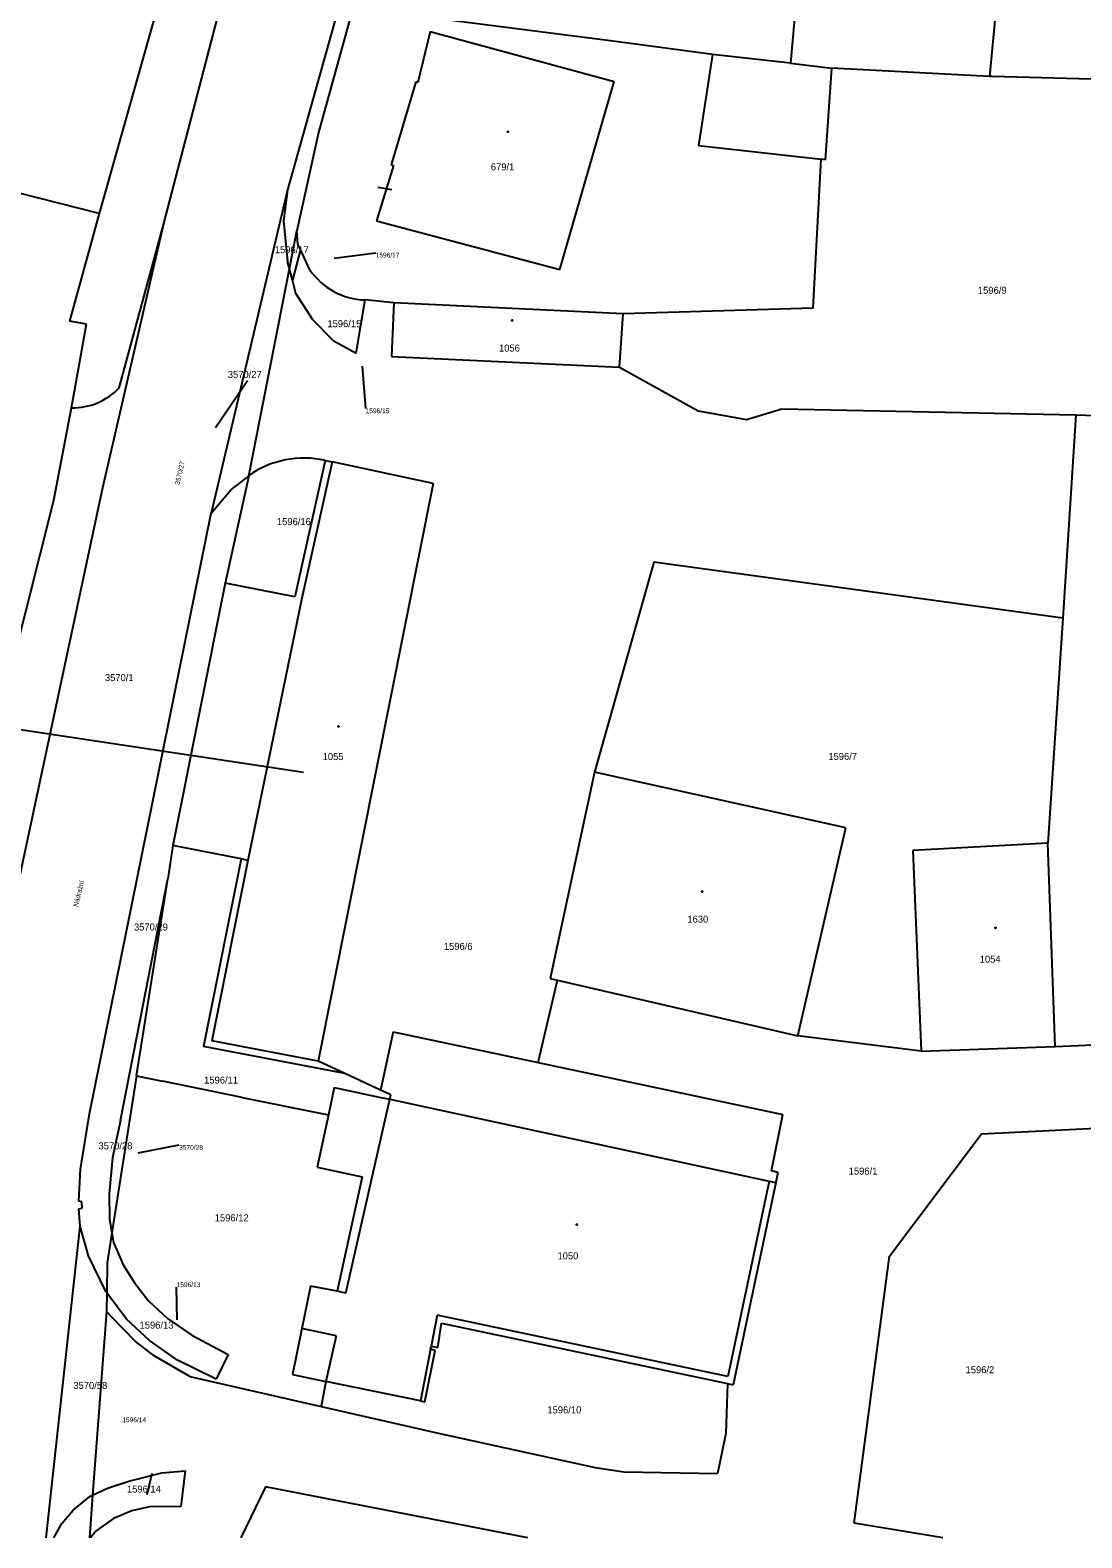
# Model space of a CAD drawing. Extents: x -866624 to -866276, y -1050208 to -1049940.
# Drawn here: x -866468.3 to -866393.3, y -1050208.1 to -1050100.7 of the extents above; entities that cross this region are included whole.
import ezdxf

# ---------------------------------------------------------------- set-up
doc = ezdxf.new("R2010")
doc.units = 0
for name, color, linetype in [('_FORMATY', 7, 'Continuous'), ('Default', 7, 'Continuous'), ('Hranice', 7, 'Continuous'), ('Hranice další', 7, 'Continuous'), ('Hranice-budov', 7, 'Continuous'), ('nazvy-ulic-tok', 7, 'Continuous'), ('Parcela-pozemkova', 7, 'Continuous'), ('Parcela-stavebni', 7, 'Continuous'), ('Parcelni-cisla-pomocna', 7, 'Continuous'), ('znacky-budov', 7, 'Continuous')]:
    doc.layers.add(name, color=color, linetype=linetype)

# ---------------------------------------------------------------- blocks, each defined once
blk = doc.blocks.new('s_zdena')
at = {"layer": 'Default'}
blk.add_circle((0, 0), 0.175, dxfattribs=at)
for start, end in [(0, 180), (180, 0)]:
    blk.add_arc((0, 0), 0.0875, start, end, dxfattribs=at)

msp = doc.modelspace()

# ---------------------------------------------------------------- linework, layer by layer
at = {"layer": '_FORMATY'}
for p, q in [((-866442.54, -1050112.04), (-866443.53, -1050111.89)), ((-866507.55, -1050144.69), (-866448.82, -1050153.56))]:
    msp.add_line(p, q, dxfattribs=at)
at = {"layer": 'Hranice'}
for p, q in [((-866439.93, -1050076.25), (-866449.97, -1050112.04)), ((-866457.96, -1050094.49), (-866463.4, -1050113.74)), ((-866458.78, -1050114.45), (-866453.82, -1050095.39)), ((-866413.54, -1050096.51), (-866414.11, -1050103.03)), ((-866445.48, -1050099.71), (-866447.75, -1050107.96)), ((-866426.4, -1050101.5), (-866441.63, -1050099.54)), ((-866419.67, -1050102.39), (-866426.4, -1050101.5)), ((-866414.11, -1050103.03), (-866419.67, -1050102.39)), ((-866414.11, -1050103.03), (-866411.18, -1050103.37)), ((-866411.18, -1050103.37), (-866411.64, -1050109.92)), ((-866399.92, -1050103.96), (-866411.18, -1050103.37)), ((-866399.74, -1050103.97), (-866399.92, -1050103.96)), ((-866361.55, -1050105.03), (-866399.74, -1050103.97)), ((-866447.75, -1050107.96), (-866449.3, -1050114.98)), ((-866412.49, -1050120.49), (-866411.93, -1050109.87)), ((-866411.64, -1050109.92), (-866411.93, -1050109.87)), ((-866463.4, -1050113.74), (-866470.72, -1050111.89)), ((-866449.97, -1050112.04), (-866455.4, -1050135.11)), ((-866449.97, -1050112.04), (-866450.26, -1050114.25)), ((-866463.4, -1050113.74), (-866465.5, -1050121.42)), ((-866450.26, -1050114.25), (-866449.97, -1050117.16)), ((-866463.14, -1050133.28), (-866458.78, -1050114.45)), ((-866461.96, -1050126.16), (-866458.78, -1050114.45)), ((-866449.83, -1050117.68), (-866449.3, -1050114.98)), ((-866449.24, -1050115.91), (-866449.3, -1050114.98)), ((-866449.05, -1050116.31), (-866449.62, -1050118.48)), ((-866449.05, -1050116.31), (-866449.24, -1050115.91)), ((-866448.37, -1050117.75), (-866449.05, -1050116.31)), ((-866449.83, -1050117.68), (-866449.97, -1050117.16)), ((-866452.73, -1050132.43), (-866449.83, -1050117.68)), ((-866449.62, -1050118.48), (-866449.83, -1050117.68)), ((-866449.36, -1050119.44), (-866449.62, -1050118.48)), ((-866448.15, -1050121.32), (-866449.36, -1050119.44)), ((-866445.07, -1050123.7), (-866444.43, -1050119.9)), ((-866442.38, -1050120.11), (-866444.43, -1050119.9)), ((-866442.38, -1050120.11), (-866442.56, -1050123.94)), ((-866426.04, -1050120.9), (-866442.38, -1050120.11)), ((-866412.49, -1050120.49), (-866426.04, -1050120.9)), ((-866464.29, -1050121.63), (-866465.5, -1050121.42)), ((-866465.37, -1050127.59), (-866464.29, -1050121.63)), ((-866446.7, -1050122.79), (-866448.15, -1050121.32)), ((-866426.3, -1050124.7), (-866426.04, -1050120.9)), ((-866446.7, -1050122.79), (-866445.07, -1050123.7)), ((-866442.56, -1050123.94), (-866426.3, -1050124.7)), ((-866426.3, -1050124.7), (-866420.7, -1050127.81)), ((-866466.62, -1050134.17), (-866465.37, -1050127.59)), ((-866420.7, -1050127.81), (-866417.25, -1050128.43)), ((-866417.25, -1050128.43), (-866414.73, -1050127.67)), ((-866414.73, -1050127.67), (-866393.77, -1050128.08)), ((-866393.77, -1050128.08), (-866394.7, -1050142.59)), ((-866393.77, -1050128.08), (-866384.76, -1050128.41)), ((-866447.28, -1050131.34), (-866449.44, -1050141.06)), ((-866447.28, -1050131.34), (-866446.79, -1050131.44)), ((-866439.57, -1050132.99), (-866446.79, -1050131.44)), ((-866452.73, -1050132.43), (-866454.42, -1050140.08)), ((-866452.73, -1050132.43), (-866453.96, -1050133.39)), ((-866470.92, -1050169.71), (-866463.14, -1050133.28)), ((-866455.4, -1050135.11), (-866453.96, -1050133.39)), ((-866439.57, -1050132.99), (-866447.77, -1050174.17)), ((-866469.64, -1050146.17), (-866466.62, -1050134.17)), ((-866464.08, -1050177.93), (-866455.4, -1050135.11)), ((-866423.85, -1050138.6), (-866428.09, -1050153.56)), ((-866394.7, -1050142.59), (-866423.85, -1050138.6)), ((-866454.42, -1050140.08), (-866458.13, -1050158.79)), ((-866449.44, -1050141.06), (-866454.42, -1050140.08)), ((-866394.7, -1050142.59), (-866395.76, -1050158.62)), ((-866428.09, -1050153.56), (-866431.25, -1050168.28)), ((-866410.17, -1050157.53), (-866428.09, -1050153.56)), ((-866413.58, -1050172.35), (-866410.17, -1050157.53)), ((-866458.13, -1050158.79), (-866458.5, -1050161.17)), ((-866453.28, -1050159.75), (-866458.13, -1050158.79)), ((-866395.76, -1050158.62), (-866405.39, -1050159.15)), ((-866405.39, -1050159.15), (-866404.79, -1050173.45)), ((-866395.24, -1050173.11), (-866395.76, -1050158.62)), ((-866453.28, -1050159.75), (-866455.96, -1050173.12)), ((-866461.88, -1050178.4), (-866458.5, -1050161.17)), ((-866460.72, -1050175.21), (-866458.5, -1050161.17)), ((-866432.09, -1050174.26), (-866430.72, -1050168.4)), ((-866431.25, -1050168.28), (-866430.72, -1050168.4)), ((-866430.72, -1050168.4), (-866413.58, -1050172.35)), ((-866442.44, -1050172.07), (-866443.33, -1050176.24)), ((-866442.44, -1050172.07), (-866432.09, -1050174.26)), ((-866404.79, -1050173.45), (-866413.58, -1050172.35)), ((-866395.24, -1050173.11), (-866377.47, -1050172.35)), ((-866445.88, -1050175.05), (-866455.96, -1050173.12)), ((-866404.79, -1050173.45), (-866395.24, -1050173.11)), ((-866445.88, -1050175.05), (-866447.77, -1050174.17)), ((-866432.09, -1050174.26), (-866414.65, -1050177.96)), ((-866460.72, -1050175.21), (-866462.48, -1050186.4)), ((-866460.72, -1050175.21), (-866458.88, -1050175.59)), ((-866453.2, -1050176.75), (-866458.88, -1050175.59)), ((-866443.33, -1050176.24), (-866445.88, -1050175.05)), ((-866446.63, -1050176.04), (-866447.05, -1050177.99)), ((-866446.63, -1050176.04), (-866443.43, -1050176.72)), ((-866442.61, -1050176.57), (-866443.33, -1050176.24)), ((-866442.68, -1050176.88), (-866442.61, -1050176.57)), ((-866453.2, -1050176.75), (-866447.05, -1050177.99)), ((-866443.43, -1050176.72), (-866442.68, -1050176.88)), ((-866400.49, -1050179.35), (-866363.72, -1050177.49)), ((-866464.73, -1050181.87), (-866464.08, -1050177.93)), ((-866461.88, -1050178.4), (-866462.45, -1050181.02)), ((-866447.05, -1050177.99), (-866447.84, -1050181.72)), ((-866415.46, -1050181.99), (-866414.65, -1050177.96)), ((-866407.05, -1050188.06), (-866400.49, -1050179.35)), ((-866464.85, -1050184.15), (-866464.73, -1050181.87)), ((-866462.45, -1050181.02), (-866462.67, -1050183.63)), ((-866447.84, -1050181.72), (-866444.64, -1050182.4)), ((-866415, -1050182.1), (-866415.46, -1050181.99)), ((-866444.64, -1050182.4), (-866446.42, -1050190.57)), ((-866415.15, -1050182.82), (-866418.19, -1050197.23)), ((-866415, -1050182.1), (-866415.15, -1050182.82)), ((-866464.63, -1050184.19), (-866464.85, -1050184.15)), ((-866464.61, -1050184.64), (-866464.63, -1050184.19)), ((-866462.67, -1050183.63), (-866462.66, -1050185.42)), ((-866464.85, -1050184.69), (-866464.61, -1050184.64)), ((-866464.74, -1050185.93), (-866464.85, -1050184.69)), ((-866467.17, -1050208.15), (-866464.74, -1050185.93)), ((-866464.15, -1050188.03), (-866464.74, -1050185.93)), ((-866462.66, -1050185.42), (-866462.48, -1050186.4)), ((-866462.48, -1050186.4), (-866462.82, -1050188.54)), ((-866462.48, -1050186.4), (-866462.36, -1050187.09)), ((-866462.36, -1050187.09), (-866461.69, -1050188.68)), ((-866462.92, -1050190.59), (-866464.15, -1050188.03)), ((-866409.56, -1050207.1), (-866407.05, -1050188.06)), ((-866462.82, -1050188.54), (-866462.84, -1050190.69)), ((-866461.69, -1050188.68), (-866460.85, -1050189.99)), ((-866462.84, -1050190.69), (-866462.92, -1050190.59)), ((-866460.85, -1050189.99), (-866459.87, -1050191.25)), ((-866448.32, -1050190.21), (-866448.94, -1050193.22)), ((-866446.42, -1050190.57), (-866448.32, -1050190.21)), ((-866462.84, -1050190.69), (-866462.86, -1050192.02)), ((-866461.45, -1050192.56), (-866462.84, -1050190.69)), ((-866459.87, -1050191.25), (-866458.52, -1050192.51)), ((-866462.86, -1050192.02), (-866463.86, -1050205.1)), ((-866462.86, -1050192.02), (-866462.51, -1050192.39)), ((-866462.51, -1050192.39), (-866460.83, -1050194.12)), ((-866459.81, -1050194.08), (-866461.45, -1050192.56)), ((-866458.52, -1050192.51), (-866456.79, -1050193.7)), ((-866456.79, -1050193.7), (-866454.19, -1050195.07)), ((-866448.94, -1050193.22), (-866449.61, -1050196.5)), ((-866439.26, -1050194.58), (-866438.98, -1050192.84)), ((-866438.98, -1050192.84), (-866418.6, -1050197.15)), ((-866459.46, -1050195.17), (-866460.83, -1050194.12)), ((-866457.8, -1050195.49), (-866459.81, -1050194.08)), ((-866440.18, -1050198.44), (-866439.43, -1050194.78)), ((-866439.77, -1050194.7), (-866439.73, -1050194.49)), ((-866439.43, -1050194.78), (-866439.77, -1050194.7)), ((-866439.73, -1050194.49), (-866439.26, -1050194.58)), ((-866456.93, -1050196.65), (-866459.46, -1050195.17)), ((-866455.05, -1050196.84), (-866457.8, -1050195.49)), ((-866454.19, -1050195.07), (-866455.05, -1050196.84)), ((-866456.93, -1050196.65), (-866447.56, -1050198.78)), ((-866449.61, -1050196.5), (-866447.23, -1050196.99)), ((-866447.23, -1050196.99), (-866447.56, -1050198.78)), ((-866440.48, -1050198.38), (-866447.23, -1050196.99)), ((-866418.6, -1050197.15), (-866418.73, -1050200.71)), ((-866418.6, -1050197.15), (-866418.19, -1050197.23)), ((-866447.56, -1050198.78), (-866439.1, -1050200.7)), ((-866440.48, -1050198.38), (-866440.18, -1050198.44)), ((-866439.1, -1050200.7), (-866428.03, -1050203.13)), ((-866418.73, -1050200.71), (-866419.32, -1050203.56)), ((-866461.28, -1050204.1), (-866458.92, -1050203.51)), ((-866458.92, -1050203.51), (-866457.26, -1050203.36)), ((-866457.26, -1050203.36), (-866457.58, -1050205.91)), ((-866428.03, -1050203.13), (-866426, -1050203.44)), ((-866426, -1050203.44), (-866419.32, -1050203.56)), ((-866463.86, -1050205.1), (-866462.8, -1050204.6)), ((-866462.8, -1050204.6), (-866461.28, -1050204.1)), ((-866451.53, -1050204.52), (-866453.29, -1050208.15)), ((-866432.83, -1050208.15), (-866451.53, -1050204.52)), ((-866465.25, -1050206.18), (-866464.05, -1050205.19)), ((-866463.86, -1050205.1), (-866464.09, -1050208.15)), ((-866464.05, -1050205.19), (-866463.86, -1050205.1)), ((-866466.06, -1050207.13), (-866465.25, -1050206.18)), ((-866462.37, -1050206.77), (-866463.61, -1050207.64)), ((-866461.06, -1050206.23), (-866462.37, -1050206.77)), ((-866459.8, -1050205.93), (-866461.06, -1050206.23)), ((-866457.58, -1050205.91), (-866459.8, -1050205.93)), ((-866466.63, -1050208.15), (-866466.06, -1050207.13)), ((-866463.61, -1050207.64), (-866464.02, -1050208.15)), ((-866403.26, -1050208.15), (-866409.56, -1050207.1))]:
    msp.add_line(p, q, dxfattribs=at)
for centre, radius, start, end in [((-866444.3, -1050114.97), 4.93, 214.2918, 268.4669), ((-866465.29, -1050122.99), 4.6, 269.0646, 316.4374), ((-866448.79, -1050137.98), 6.81, 77.225, 125.3949)]:
    msp.add_arc(centre, radius, start, end, dxfattribs=at)
at = {"layer": 'Hranice další'}
for p, q in [((-866399.34, -1050097.9), (-866399.92, -1050103.96)), ((-866439.79, -1050100.75), (-866440.67, -1050104.39)), ((-866439.79, -1050100.75), (-866426.67, -1050104.32)), ((-866419.67, -1050102.39), (-866420.66, -1050108.88)), ((-866440.82, -1050104.35), (-866442.57, -1050110.27)), ((-866440.67, -1050104.39), (-866440.82, -1050104.35)), ((-866430.55, -1050117.72), (-866426.67, -1050104.32)), ((-866420.66, -1050108.88), (-866411.93, -1050109.87)), ((-866442.42, -1050110.31), (-866443.61, -1050114.25)), ((-866442.57, -1050110.27), (-866442.42, -1050110.31)), ((-866443.61, -1050114.25), (-866430.55, -1050117.72)), ((-866446.79, -1050131.44), (-866448.95, -1050141.16)), ((-866448.95, -1050141.16), (-866452.79, -1050159.85)), ((-866452.79, -1050159.85), (-866455.37, -1050172.72)), ((-866452.79, -1050159.85), (-866453.28, -1050159.75)), ((-866447.77, -1050174.17), (-866455.37, -1050172.72)), ((-866445.81, -1050190.7), (-866442.68, -1050176.88)), ((-866442.68, -1050176.88), (-866415.64, -1050182.72)), ((-866415.64, -1050182.72), (-866418.58, -1050196.64)), ((-866415.64, -1050182.72), (-866415.15, -1050182.82)), ((-866445.81, -1050190.7), (-866446.42, -1050190.57)), ((-866439.3, -1050192.26), (-866439.73, -1050194.49)), ((-866418.58, -1050196.64), (-866439.3, -1050192.26)), ((-866446.5, -1050193.75), (-866448.94, -1050193.22)), ((-866446.5, -1050193.75), (-866447.23, -1050196.99)), ((-866439.77, -1050194.7), (-866440.48, -1050198.38))]:
    msp.add_line(p, q, dxfattribs=at)
at = {"layer": 'Hranice-budov'}
for p, q in [((-866439.79, -1050100.75), (-866440.67, -1050104.39)), ((-866439.79, -1050100.75), (-866426.67, -1050104.32)), ((-866440.82, -1050104.35), (-866442.57, -1050110.27)), ((-866440.67, -1050104.39), (-866440.82, -1050104.35)), ((-866430.55, -1050117.72), (-866426.67, -1050104.32)), ((-866442.42, -1050110.31), (-866443.61, -1050114.25)), ((-866442.57, -1050110.27), (-866442.42, -1050110.31)), ((-866443.61, -1050114.25), (-866430.55, -1050117.72)), ((-866442.38, -1050120.11), (-866442.56, -1050123.94)), ((-866426.04, -1050120.9), (-866442.38, -1050120.11)), ((-866426.3, -1050124.7), (-866426.04, -1050120.9)), ((-866442.56, -1050123.94), (-866426.3, -1050124.7)), ((-866446.79, -1050131.44), (-866448.95, -1050141.16)), ((-866439.57, -1050132.99), (-866446.79, -1050131.44)), ((-866439.57, -1050132.99), (-866447.77, -1050174.17)), ((-866448.95, -1050141.16), (-866452.79, -1050159.85)), ((-866428.09, -1050153.56), (-866431.25, -1050168.28)), ((-866410.17, -1050157.53), (-866428.09, -1050153.56)), ((-866413.58, -1050172.35), (-866410.17, -1050157.53)), ((-866395.76, -1050158.62), (-866405.39, -1050159.15)), ((-866405.39, -1050159.15), (-866404.79, -1050173.45)), ((-866395.24, -1050173.11), (-866395.76, -1050158.62)), ((-866452.79, -1050159.85), (-866455.37, -1050172.72)), ((-866431.25, -1050168.28), (-866430.72, -1050168.4)), ((-866430.72, -1050168.4), (-866413.58, -1050172.35)), ((-866447.77, -1050174.17), (-866455.37, -1050172.72)), ((-866404.79, -1050173.45), (-866395.24, -1050173.11)), ((-866445.81, -1050190.7), (-866442.68, -1050176.88)), ((-866442.68, -1050176.88), (-866415.64, -1050182.72)), ((-866415.64, -1050182.72), (-866418.58, -1050196.64)), ((-866448.32, -1050190.21), (-866448.94, -1050193.22)), ((-866446.42, -1050190.57), (-866448.32, -1050190.21)), ((-866445.81, -1050190.7), (-866446.42, -1050190.57)), ((-866439.3, -1050192.26), (-866439.73, -1050194.49)), ((-866418.58, -1050196.64), (-866439.3, -1050192.26)), ((-866446.5, -1050193.75), (-866448.94, -1050193.22)), ((-866446.5, -1050193.75), (-866447.23, -1050196.99)), ((-866439.77, -1050194.7), (-866440.48, -1050198.38)), ((-866439.77, -1050194.7), (-866439.73, -1050194.49)), ((-866440.48, -1050198.38), (-866447.23, -1050196.99))]:
    msp.add_line(p, q, dxfattribs=at)
at = {"layer": 'Parcelni-cisla-pomocna'}
for p, q in [((-866446.65, -1050116.91), (-866443.68, -1050116.53)), ((-866444.64, -1050124.61), (-866444.4, -1050127.63)), ((-866455.09, -1050128.98), (-866452.81, -1050125.63)), ((-866460.6, -1050180.71), (-866457.69, -1050180.14)), ((-866457.83, -1050192.6), (-866457.87, -1050190.27)), ((-866459.64, -1050203.57), (-866459.99, -1050205.09))]:
    msp.add_line(p, q, dxfattribs=at)

# ---------------------------------------------------------------- block references
at = {"layer": 'znacky-budov', "xscale": 0.2, "yscale": 0.20000000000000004}
for p in [(-866434.26, -1050107.91), (-866433.94, -1050121.36), (-866446.34, -1050150.3), (-866420.41, -1050162.07), (-866399.5, -1050164.67), (-866429.33, -1050185.81)]:
    msp.add_blockref('s_zdena', p, dxfattribs=at)

# ---------------------------------------------------------------- texts
at = {"layer": 'nazvy-ulic-tok'}
msp.add_text('Nádražní', height=0.34, rotation=76.6916, dxfattribs=at).set_placement((-866464.91, -1050163.19))
at = {"layer": 'Parcela-pozemkova'}
for s, p in [('1596/17', (-866450.87, -1050116.57)), ('1596/9', (-866400.75, -1050119.46)), ('1596/15', (-866447.12, -1050121.84)), ('3570/27', (-866454.22, -1050125.46)), ('1596/16', (-866450.72, -1050135.95)), ('3570/1', (-866462.98, -1050147.07)), ('1596/7', (-866411.41, -1050152.69)), ('3570/29', (-866460.91, -1050164.85)), ('1596/6', (-866438.82, -1050166.23)), ('1596/11', (-866455.91, -1050175.76)), ('3570/28', (-866463.44, -1050180.45)), ('1596/1', (-866409.96, -1050182.25)), ('1596/12', (-866455.15, -1050185.58)), ('1596/13', (-866460.51, -1050193.23)), ('1596/2', (-866401.63, -1050196.41)), ('3570/58', (-866465.23, -1050197.53)), ('1596/10', (-866431.44, -1050199.27)), ('1596/14', (-866461.41, -1050204.92))]:
    msp.add_text(s, height=0.5, dxfattribs=at).set_placement(p)
at = {"layer": 'Parcela-stavebni'}
for s, p in [('679/1', (-866435.47, -1050110.66)), ('1056', (-866434.89, -1050123.58)), ('1055', (-866447.46, -1050152.7)), ('1630', (-866421.46, -1050164.29)), ('1054', (-866400.62, -1050167.14)), ('1050', (-866430.72, -1050188.29))]:
    msp.add_text(s, height=0.5, dxfattribs=at).set_placement(p)
at = {"layer": 'Parcelni-cisla-pomocna'}
for s, p in [('1596/17', (-866443.68, -1050116.87)), ('1596/15', (-866444.4, -1050127.97)), ('3570/28', (-866457.69, -1050180.48)), ('1596/13', (-866457.87, -1050190.27)), ('1596/14', (-866461.74, -1050199.9))]:
    msp.add_text(s, height=0.34, dxfattribs=at).set_placement(p)
msp.add_text('3570/27', height=0.34, rotation=77.1201, dxfattribs=at).set_placement((-866457.67, -1050133.1))

doc.saveas('drawing.dxf')
